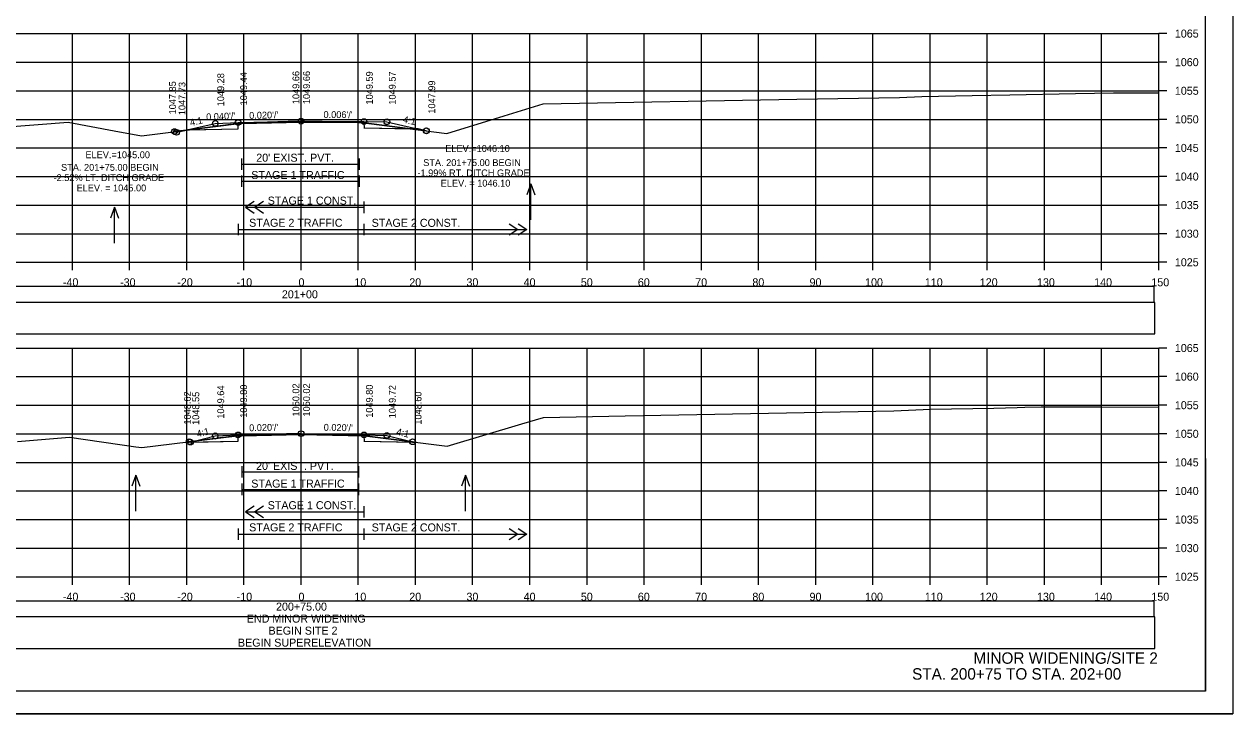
# Model space of a CAD drawing. Extents: x 1370565 to 1374448, y 301010 to 304637.
# Drawn here: x 1373320.4 to 1373531.7, y 301085 to 301205.6 of the extents above; entities that cross this region are included whole.
import ezdxf

# ---------------------------------------------------------------- set-up
doc = ezdxf.new("R2010")
doc.units = 0
for name, color, linetype in [('Default', 7, 'Continuous'), ('R_Alt Surface', 7, 'Continuous'), ('R_Axis', 7, 'Continuous'), ('R_Axis Annot', 7, 'Continuous'), ('R_Border', 7, 'Continuous'), ('R_Contours', 7, 'Continuous'), ('R_Draft', 7, 'Continuous'), ('R_Exist Surface', 7, 'Continuous'), ('R_Fin Surface', 7, 'Continuous'), ('R_Grid', 7, 'Continuous'), ('R_No Plot', 7, 'Continuous'), ('R_Water', 7, 'Continuous'), ('R_Water Annot', 7, 'Continuous'), ('R_Xsect Elev', 7, 'Continuous'), ('R_Xsect Slope', 7, 'Continuous')]:
    doc.layers.add(name, color=color, linetype=linetype)

msp = doc.modelspace()

# ---------------------------------------------------------------- linework, layer by layer
at = {"layer": 'Default'}
for points in [[(1373219.61, 301157), (1373518.02, 301157), (1373518.02, 301159.71), (1373219.61, 301159.71)], [(1373219.61, 301102), (1373518.02, 301102), (1373518.02, 301104.71), (1373219.61, 301104.71)]]:
    msp.add_lwpolyline(points, close=True, dxfattribs=at)
at = {"layer": 'R_Alt Surface'}
for points in [[(1373349.02, 301187.14), (1373357.81, 301187.32), (1373357.8, 301187.32), (1373357.81, 301188.23), (1373368.81, 301188.45), (1373379.81, 301188.39), (1373379.82, 301187.47), (1373379.81, 301187.47), (1373389.26, 301187.28)], [(1373360.61, 301174.57), (1373359.11, 301173.57), (1373360.61, 301172.57)], [(1373362.21, 301174.57), (1373360.71, 301173.57), (1373362.21, 301172.57)], [(1373359.11, 301173.57), (1373379.81, 301173.57)], [(1373357.81, 301170.7), (1373357.81, 301168.7)], [(1373357.81, 301169.7), (1373379.81, 301169.7)], [(1373379.81, 301170.7), (1373379.81, 301168.7)], [(1373379.81, 301170.7), (1373379.81, 301168.7)], [(1373379.81, 301169.7), (1373408.3, 301169.7)], [(1373405.21, 301170.7), (1373406.71, 301169.7), (1373405.21, 301168.7)], [(1373406.8, 301170.7), (1373408.3, 301169.7), (1373406.8, 301168.7)], [(1373348.57, 301132.49), (1373357.81, 301132.68), (1373357.8, 301132.68), (1373357.81, 301133.6), (1373368.81, 301133.82), (1373379.81, 301133.6), (1373379.82, 301132.68), (1373379.81, 301132.68), (1373388.79, 301132.5)], [(1373360.61, 301121.29), (1373359.11, 301120.29), (1373360.61, 301119.29)], [(1373362.21, 301121.29), (1373360.71, 301120.29), (1373362.21, 301119.29)], [(1373359.11, 301120.29), (1373379.81, 301120.29)], [(1373357.81, 301117.42), (1373357.81, 301115.42)], [(1373379.81, 301117.42), (1373379.81, 301115.42)], [(1373379.81, 301117.42), (1373379.81, 301115.42)], [(1373405.21, 301117.42), (1373406.71, 301116.42), (1373405.21, 301115.42)], [(1373406.8, 301117.42), (1373408.3, 301116.42), (1373406.8, 301115.42)], [(1373357.81, 301116.42), (1373379.81, 301116.42)], [(1373379.81, 301116.42), (1373408.3, 301116.42)]]:
    msp.add_lwpolyline(points, dxfattribs=at)
at = {"layer": 'R_Axis'}
for p, q in [((1373518.81, 301163.96), (1373518.81, 301203.96)), ((1373520.21, 301203.96), (1373518.81, 301203.96)), ((1373520.21, 301198.96), (1373518.81, 301198.96)), ((1373520.21, 301193.96), (1373518.81, 301193.96)), ((1373520.21, 301188.96), (1373518.81, 301188.96)), ((1373520.21, 301183.96), (1373518.81, 301183.96)), ((1373520.21, 301178.96), (1373518.81, 301178.96)), ((1373520.21, 301173.96), (1373518.81, 301173.96)), ((1373520.21, 301168.96), (1373518.81, 301168.96)), ((1373218.81, 301163.96), (1373518.81, 301163.96)), ((1373328.81, 301162.56), (1373328.81, 301163.96)), ((1373338.81, 301162.56), (1373338.81, 301163.96)), ((1373348.81, 301162.56), (1373348.81, 301163.96)), ((1373358.81, 301162.56), (1373358.81, 301163.96)), ((1373368.81, 301162.56), (1373368.81, 301163.96)), ((1373378.81, 301162.56), (1373378.81, 301163.96)), ((1373388.81, 301162.56), (1373388.81, 301163.96)), ((1373398.81, 301162.56), (1373398.81, 301163.96)), ((1373408.81, 301162.56), (1373408.81, 301163.96)), ((1373418.81, 301162.56), (1373418.81, 301163.96)), ((1373428.81, 301162.56), (1373428.81, 301163.96)), ((1373438.81, 301162.56), (1373438.81, 301163.96)), ((1373448.81, 301162.56), (1373448.81, 301163.96)), ((1373458.81, 301162.56), (1373458.81, 301163.96)), ((1373468.81, 301162.56), (1373468.81, 301163.96)), ((1373478.81, 301162.56), (1373478.81, 301163.96)), ((1373488.81, 301162.56), (1373488.81, 301163.96)), ((1373498.81, 301162.56), (1373498.81, 301163.96)), ((1373508.81, 301162.56), (1373508.81, 301163.96)), ((1373518.81, 301162.56), (1373518.81, 301163.96)), ((1373520.21, 301163.96), (1373518.81, 301163.96)), ((1373518.81, 301108.96), (1373518.81, 301148.96)), ((1373520.21, 301148.96), (1373518.81, 301148.96)), ((1373520.21, 301143.96), (1373518.81, 301143.96)), ((1373520.21, 301138.96), (1373518.81, 301138.96)), ((1373520.21, 301133.96), (1373518.81, 301133.96)), ((1373520.21, 301128.96), (1373518.81, 301128.96)), ((1373520.21, 301123.96), (1373518.81, 301123.96)), ((1373520.21, 301118.96), (1373518.81, 301118.96)), ((1373520.21, 301113.96), (1373518.81, 301113.96)), ((1373218.81, 301108.96), (1373518.81, 301108.96)), ((1373328.81, 301107.56), (1373328.81, 301108.96)), ((1373338.81, 301107.56), (1373338.81, 301108.96)), ((1373348.81, 301107.56), (1373348.81, 301108.96)), ((1373358.81, 301107.56), (1373358.81, 301108.96)), ((1373368.81, 301107.56), (1373368.81, 301108.96)), ((1373378.81, 301107.56), (1373378.81, 301108.96)), ((1373388.81, 301107.56), (1373388.81, 301108.96)), ((1373398.81, 301107.56), (1373398.81, 301108.96)), ((1373408.81, 301107.56), (1373408.81, 301108.96)), ((1373418.81, 301107.56), (1373418.81, 301108.96)), ((1373428.81, 301107.56), (1373428.81, 301108.96)), ((1373438.81, 301107.56), (1373438.81, 301108.96)), ((1373448.81, 301107.56), (1373448.81, 301108.96)), ((1373458.81, 301107.56), (1373458.81, 301108.96)), ((1373468.81, 301107.56), (1373468.81, 301108.96)), ((1373478.81, 301107.56), (1373478.81, 301108.96)), ((1373488.81, 301107.56), (1373488.81, 301108.96)), ((1373498.81, 301107.56), (1373498.81, 301108.96)), ((1373508.81, 301107.56), (1373508.81, 301108.96)), ((1373518.81, 301107.56), (1373518.81, 301108.96)), ((1373520.21, 301108.96), (1373518.81, 301108.96))]:
    msp.add_line(p, q, dxfattribs=at)
for points in [[(1373358.4, 301182.13), (1373358.4, 301180.13)], [(1373358.4, 301181.13), (1373378.94, 301181.13)], [(1373378.94, 301182.13), (1373378.94, 301180.13)], [(1373358.4, 301179.14), (1373358.4, 301177.14)], [(1373358.4, 301178.14), (1373378.94, 301178.14)], [(1373378.94, 301179.14), (1373378.94, 301177.14)], [(1373379.81, 301174.57), (1373379.81, 301172.57)], [(1373358.43, 301128.32), (1373358.43, 301126.32)], [(1373358.43, 301127.32), (1373378.84, 301127.32)], [(1373378.84, 301128.32), (1373378.84, 301126.32)], [(1373358.43, 301125.24), (1373358.43, 301123.24)], [(1373378.84, 301125.24), (1373378.84, 301123.24)], [(1373358.43, 301124.24), (1373378.84, 301124.24)], [(1373379.81, 301121.29), (1373379.81, 301119.29)]]:
    msp.add_lwpolyline(points, dxfattribs=at)
at = {"layer": 'R_Border'}
for q in [(1373526.99, 301294.42), (1373210.81, 301088.96)]:
    msp.add_line((1373526.99, 301088.96), q, dxfattribs=at)
at = {"layer": 'R_Contours'}
for p, q in [((1373348.75, 301187.08), (1373346.67, 301186.82)), ((1373349.02, 301187.14), (1373348.75, 301187.08)), ((1373348.75, 301187.08), (1373349.02, 301187.12)), ((1373349.02, 301187.12), (1373349.27, 301187.15)), ((1373349.27, 301187.15), (1373349.02, 301187.14)), ((1373357.81, 301188.24), (1373349.27, 301187.15)), ((1373349.27, 301187.15), (1373357.81, 301187.32)), ((1373358.43, 301188.32), (1373357.81, 301188.24)), ((1373357.81, 301188.23), (1373358.43, 301188.25)), ((1373357.81, 301187.32), (1373357.81, 301188.23)), ((1373358.43, 301188.25), (1373368.81, 301188.45)), ((1373368.81, 301188.45), (1373378.84, 301188.39)), ((1373379.55, 301188.39), (1373378.84, 301188.48)), ((1373378.84, 301188.39), (1373379.55, 301188.39)), ((1373379.81, 301188.36), (1373379.82, 301187.47)), ((1373379.82, 301187.47), (1373387.91, 301187.31)), ((1373389.26, 301187.28), (1373387.91, 301187.31)), ((1373387.91, 301187.31), (1373390.69, 301186.95)), ((1373390.69, 301186.96), (1373389.26, 301187.28)), ((1373358.31, 301133.69), (1373357.81, 301133.63)), ((1373357.81, 301133.6), (1373358.29, 301133.6)), ((1373358.29, 301133.6), (1373358.45, 301133.61)), ((1373358.45, 301133.61), (1373368.81, 301133.82)), ((1373368.81, 301133.98), (1373368.81, 301133.82)), ((1373368.81, 301133.82), (1373379.81, 301133.6)), ((1373380.83, 301133.51), (1373379.82, 301133.64)), ((1373348.76, 301132.5), (1373348.95, 301132.5)), ((1373348.95, 301132.5), (1373349.26, 301132.51)), ((1373349.26, 301132.58), (1373348.96, 301132.54)), ((1373349.44, 301132.6), (1373349.26, 301132.58)), ((1373349.26, 301132.58), (1373349.45, 301132.51)), ((1373350.17, 301132.69), (1373349.44, 301132.6)), ((1373349.45, 301132.51), (1373350.17, 301132.69)), ((1373350.17, 301132.69), (1373349.94, 301132.63)), ((1373353.68, 301133.12), (1373350.17, 301132.69)), ((1373388.3, 301132.56), (1373380.83, 301133.51)), ((1373388.31, 301132.56), (1373388.3, 301132.56)), ((1373388.79, 301132.5), (1373388.31, 301132.56)), ((1373388.31, 301132.51), (1373388.79, 301132.5))]:
    msp.add_line(p, q, dxfattribs=at)
for points in [[(1373366.55, 301188.58), (1373361.14, 301188.4), (1373358.43, 301188.32)], [(1373369.3, 301188.62), (1373368.81, 301188.62), (1373368.27, 301188.61), (1373366.55, 301188.58)], [(1373378.84, 301188.48), (1373375.72, 301188.54), (1373369.3, 301188.62)], [(1373346.67, 301186.82), (1373347.04, 301186.69), (1373348.75, 301187.08)], [(1373349.02, 301187.14), (1373349.02, 301187.12)], [(1373349.02, 301187.12), (1373349.02, 301187.14)], [(1373357.81, 301188.23), (1373357.81, 301188.24)], [(1373357.81, 301188.24), (1373357.81, 301188.23)], [(1373358.43, 301188.32), (1373358.43, 301188.25)], [(1373358.43, 301188.25), (1373358.43, 301188.32)], [(1373378.84, 301188.39), (1373378.84, 301188.48)], [(1373378.84, 301188.48), (1373378.84, 301188.39)], [(1373387.91, 301187.31), (1373384.71, 301187.73), (1373379.81, 301188.36)], [(1373390.69, 301186.95), (1373390.69, 301186.96)], [(1373357.81, 301133.63), (1373357.81, 301133.6)], [(1373358.45, 301133.71), (1373358.32, 301133.69), (1373358.31, 301133.69)], [(1373366.28, 301133.93), (1373359.29, 301133.73), (1373358.45, 301133.71)], [(1373358.45, 301133.71), (1373358.45, 301133.61)], [(1373358.45, 301133.61), (1373358.45, 301133.71)], [(1373368.81, 301133.98), (1373368.37, 301133.97), (1373366.28, 301133.93)], [(1373379.82, 301133.64), (1373378.92, 301133.75), (1373377.77, 301133.78), (1373368.81, 301133.98), (1373368.81, 301133.98)], [(1373379.81, 301133.6), (1373379.82, 301133.64)], [(1373379.82, 301133.64), (1373379.81, 301133.6)], [(1373379.81, 301133.6), (1373379.82, 301132.68), (1373388.31, 301132.51)], [(1373348.95, 301132.54), (1373348.76, 301132.52), (1373348.76, 301132.52)], [(1373348.95, 301132.51), (1373348.95, 301132.54)], [(1373348.95, 301132.51), (1373348.95, 301132.5)], [(1373349.26, 301132.51), (1373349.26, 301132.58)], [(1373349.44, 301132.6), (1373349.45, 301132.51)], [(1373349.45, 301132.51), (1373349.44, 301132.6)], [(1373349.95, 301132.52), (1373357.81, 301132.68), (1373357.81, 301133.26)], [(1373357.35, 301133.57), (1373357.15, 301133.55), (1373354.07, 301133.17)], [(1373388.31, 301132.51), (1373388.31, 301132.56)], [(1373388.31, 301132.56), (1373388.31, 301132.56), (1373388.31, 301132.51)]]:
    msp.add_lwpolyline(points, dxfattribs=at)
for centre, start, end in [((1373357.81, 301133.76), 341.6745, 351.6588), ((1373357.81, 301133.76), 341.6745, 351.6588), ((1373349.26, 301132.58), 187.0089, 189.2983), ((1373349.45, 301132.51), 176.614, 180), ((1373349.45, 301132.51), 180, 181.2068), ((1373349.45, 301132.51), 1.0848, 14.0363), ((1373353.81, 301133.6), 253.8235, 300.1943), ((1373357.81, 301133.76), 202.1604, 270)]:
    msp.add_arc(centre, 0.5, start, end, dxfattribs=at)
at = {"layer": 'R_Exist Surface'}
for points in [[(1373304.79, 301186.66), (1373328.1, 301188.49), (1373336.1, 301186.95), (1373340.9, 301186.09), (1373344.16, 301186.49), (1373358.43, 301188.32), (1373361.14, 301188.4), (1373368.27, 301188.63), (1373375.72, 301188.54), (1373378.84, 301188.48), (1373384.71, 301187.73), (1373394.27, 301186.49), (1373404.35, 301189.56), (1373411.16, 301191.65), (1373455.5, 301192.51), (1373473.46, 301192.8), (1373477.34, 301192.94), (1373486.19, 301193.15), (1373492.75, 301193.27), (1373504.23, 301193.48), (1373510.87, 301193.62), (1373511.82, 301193.62), (1373518.81, 301193.62)], [(1373319.24, 301132.6), (1373328.29, 301133.38), (1373339.91, 301131.69), (1373340.99, 301131.56), (1373357.15, 301133.55), (1373358.45, 301133.71), (1373359.29, 301133.73), (1373368.37, 301133.99), (1373377.77, 301133.78), (1373378.92, 301133.75), (1373380.83, 301133.51), (1373394.35, 301131.79), (1373407.39, 301135.7), (1373411.22, 301136.83), (1373425.48, 301137.09), (1373472.49, 301137.98), (1373478.85, 301138.24), (1373489.93, 301138.46), (1373494.01, 301138.58), (1373495.39, 301138.61), (1373498.22, 301138.66), (1373508.74, 301138.66), (1373518.81, 301138.61)]]:
    msp.add_lwpolyline(points, dxfattribs=at)
at = {"layer": 'R_Fin Surface'}
for points in [[(1373346.67, 301186.82), (1373347.04, 301186.69), (1373353.81, 301188.24), (1373357.81, 301188.4), (1373368.81, 301188.62), (1373379.81, 301188.56), (1373383.81, 301188.53), (1373390.69, 301186.96), (1373390.72, 301186.95)], [(1373349.26, 301132.58), (1373349.45, 301132.51), (1373353.81, 301133.6), (1373357.81, 301133.76), (1373368.81, 301133.98), (1373379.81, 301133.76), (1373383.81, 301133.68), (1373388.31, 301132.56), (1373388.32, 301132.56)]]:
    msp.add_lwpolyline(points, dxfattribs=at)
for points in [[(1373219.66, 301151.42), (1373518.08, 301151.42), (1373518.08, 301156.94), (1373219.66, 301156.94)], [(1373219.66, 301096.43), (1373518.08, 301096.43), (1373518.08, 301101.95), (1373219.66, 301101.95)]]:
    msp.add_lwpolyline(points, close=True, dxfattribs=at)
at = {"layer": 'R_Grid'}
for p, q in [((1373218.81, 301203.96), (1373518.81, 301203.96)), ((1373328.81, 301163.96), (1373328.81, 301203.96)), ((1373338.81, 301163.96), (1373338.81, 301203.96)), ((1373348.81, 301163.96), (1373348.81, 301203.96)), ((1373358.81, 301163.96), (1373358.81, 301203.96)), ((1373368.81, 301163.96), (1373368.81, 301203.96)), ((1373378.81, 301163.96), (1373378.81, 301203.96)), ((1373388.81, 301163.96), (1373388.81, 301203.96)), ((1373398.81, 301163.96), (1373398.81, 301203.96)), ((1373408.81, 301163.96), (1373408.81, 301203.96)), ((1373418.81, 301163.96), (1373418.81, 301203.96)), ((1373428.81, 301163.96), (1373428.81, 301203.96)), ((1373438.81, 301163.96), (1373438.81, 301203.96)), ((1373448.81, 301163.96), (1373448.81, 301203.96)), ((1373458.81, 301163.96), (1373458.81, 301203.96)), ((1373468.81, 301163.96), (1373468.81, 301203.96)), ((1373478.81, 301163.96), (1373478.81, 301203.96)), ((1373488.81, 301163.96), (1373488.81, 301203.96)), ((1373498.81, 301163.96), (1373498.81, 301203.96)), ((1373508.81, 301163.96), (1373508.81, 301203.96)), ((1373518.81, 301163.96), (1373518.81, 301203.96)), ((1373218.81, 301198.96), (1373518.81, 301198.96)), ((1373218.81, 301193.96), (1373518.81, 301193.96)), ((1373218.81, 301188.96), (1373518.81, 301188.96)), ((1373218.81, 301183.96), (1373518.81, 301183.96)), ((1373218.81, 301178.96), (1373518.81, 301178.96)), ((1373218.81, 301173.96), (1373518.81, 301173.96)), ((1373218.81, 301168.96), (1373518.81, 301168.96)), ((1373218.81, 301163.96), (1373518.81, 301163.96)), ((1373218.81, 301148.96), (1373518.81, 301148.96)), ((1373328.81, 301108.96), (1373328.81, 301148.96)), ((1373338.81, 301108.96), (1373338.81, 301148.96)), ((1373348.81, 301108.96), (1373348.81, 301148.96)), ((1373358.81, 301108.96), (1373358.81, 301148.96)), ((1373368.81, 301108.96), (1373368.81, 301148.96)), ((1373378.81, 301108.96), (1373378.81, 301148.96)), ((1373388.81, 301108.96), (1373388.81, 301148.96)), ((1373398.81, 301108.96), (1373398.81, 301148.96)), ((1373408.81, 301108.96), (1373408.81, 301148.96)), ((1373418.81, 301108.96), (1373418.81, 301148.96)), ((1373428.81, 301108.96), (1373428.81, 301148.96)), ((1373438.81, 301108.96), (1373438.81, 301148.96)), ((1373448.81, 301108.96), (1373448.81, 301148.96)), ((1373458.81, 301108.96), (1373458.81, 301148.96)), ((1373468.81, 301108.96), (1373468.81, 301148.96)), ((1373478.81, 301108.96), (1373478.81, 301148.96)), ((1373488.81, 301108.96), (1373488.81, 301148.96)), ((1373498.81, 301108.96), (1373498.81, 301148.96)), ((1373508.81, 301108.96), (1373508.81, 301148.96)), ((1373518.81, 301108.96), (1373518.81, 301148.96)), ((1373218.81, 301143.96), (1373518.81, 301143.96)), ((1373218.81, 301138.96), (1373518.81, 301138.96)), ((1373218.81, 301133.96), (1373518.81, 301133.96)), ((1373218.81, 301128.96), (1373518.81, 301128.96)), ((1373218.81, 301123.96), (1373518.81, 301123.96)), ((1373218.81, 301118.96), (1373518.81, 301118.96)), ((1373218.81, 301113.96), (1373518.81, 301113.96)), ((1373218.81, 301108.96), (1373518.81, 301108.96))]:
    msp.add_line(p, q, dxfattribs=at)
at = {"layer": 'R_No Plot'}
msp.add_line((1373198.41, 301084.98), (1373531.75, 301084.98), dxfattribs=at)
for points in [[(1373198.41, 301298.32), (1373531.75, 301298.32), (1373531.75, 301084.98), (1373198.41, 301084.98)], [(1373444.73, 301294.42), (1373464.35, 301294.42), (1373464.35, 301284.54), (1373480.47, 301284.54), (1373503.67, 301284.54), (1373503.67, 301251.87), (1373526.87, 301251.87), (1373526.99, 301088.96), (1373210.81, 301088.96), (1373210.81, 301294.42)]]:
    msp.add_lwpolyline(points, close=True, dxfattribs=at)
for centre in [(1373353.81, 301188.24), (1373357.81, 301188.4), (1373368.81, 301188.62), (1373379.81, 301188.56), (1373383.81, 301188.53), (1373346.67, 301186.82), (1373347.04, 301186.69), (1373390.69, 301186.96), (1373390.72, 301186.95), (1373353.81, 301133.6), (1373357.81, 301133.76), (1373368.81, 301133.98), (1373379.81, 301133.76), (1373383.81, 301133.68), (1373349.26, 301132.58), (1373349.45, 301132.51), (1373388.31, 301132.56), (1373388.32, 301132.56)]:
    msp.add_circle(centre, 0.5, dxfattribs=at)
at = {"layer": 'R_Water Annot'}
for p, q in [((1373408.97, 301177.66), (1373408.27, 301175.74)), ((1373408.97, 301171.38), (1373408.97, 301177.66)), ((1373408.97, 301177.66), (1373409.67, 301175.74)), ((1373336.16, 301173.58), (1373335.46, 301171.65)), ((1373336.16, 301167.29), (1373336.16, 301173.58)), ((1373336.16, 301173.58), (1373336.86, 301171.65)), ((1373339.89, 301126.71), (1373339.19, 301124.79)), ((1373339.89, 301120.43), (1373339.89, 301126.71)), ((1373339.89, 301126.71), (1373340.59, 301124.79)), ((1373397.57, 301126.71), (1373396.87, 301124.79)), ((1373397.57, 301120.43), (1373397.57, 301126.71)), ((1373397.57, 301126.71), (1373398.27, 301124.79))]:
    msp.add_line(p, q, dxfattribs=at)
at = {"layer": 'R_Xsect Elev'}
for p, q in [((1373368.81, 301188.62), (1373368.81, 301198.62)), ((1373368.81, 301133.98), (1373368.81, 301143.98))]:
    msp.add_line(p, q, dxfattribs=at)

# ---------------------------------------------------------------- texts
at = {"layer": 'R_Axis Annot'}
for s, p in [('1065', (1373521.61, 301203.26)), ('1060', (1373521.61, 301198.26)), ('1055', (1373521.61, 301193.26)), ('1050', (1373521.61, 301188.26)), ('1045', (1373521.61, 301183.26)), ("20' EXIST. PVT.", (1373360.97, 301181.55)), ('1040', (1373521.61, 301178.26)), ('1035', (1373521.61, 301173.26)), ('1030', (1373521.61, 301168.26)), ('1025', (1373521.61, 301163.26)), ('-40', (1373327.16, 301159.76)), ('-30', (1373337.16, 301159.76)), ('-20', (1373347.16, 301159.76)), ('-10', (1373357.55, 301159.76)), ('0', (1373368.36, 301159.76)), ('10', (1373378.13, 301159.76)), ('20', (1373387.73, 301159.76)), ('30', (1373397.73, 301159.76)), ('40', (1373407.73, 301159.76)), ('50', (1373417.73, 301159.76)), ('60', (1373427.7, 301159.76)), ('70', (1373437.73, 301159.76)), ('80', (1373447.73, 301159.76)), ('90', (1373457.73, 301159.76)), ('100', (1373467.44, 301159.76)), ('110', (1373477.89, 301159.76)), ('120', (1373487.5, 301159.76)), ('130', (1373497.5, 301159.76)), ('140', (1373507.5, 301159.76)), ('150', (1373517.5, 301159.76)), ('201+00', (1373365.45, 301157.66)), ('1065', (1373521.61, 301148.26)), ('1060', (1373521.61, 301143.26)), ('1055', (1373521.61, 301138.26)), ('1050', (1373521.61, 301133.26)), ('1045', (1373521.61, 301128.26)), ("20' EXIST. PVT.", (1373360.94, 301127.64)), ('1040', (1373521.61, 301123.26)), ('1035', (1373521.61, 301118.26)), ('1030', (1373521.61, 301113.26)), ('1025', (1373521.61, 301108.26)), ('-40', (1373327.16, 301104.76)), ('-30', (1373337.16, 301104.76)), ('-20', (1373347.16, 301104.76)), ('-10', (1373357.55, 301104.76)), ('0', (1373368.36, 301104.76)), ('10', (1373378.13, 301104.76)), ('20', (1373387.73, 301104.76)), ('30', (1373397.73, 301104.76)), ('40', (1373407.73, 301104.76)), ('50', (1373417.73, 301104.76)), ('60', (1373427.7, 301104.76)), ('70', (1373437.73, 301104.76)), ('80', (1373447.73, 301104.76)), ('90', (1373457.73, 301104.76)), ('100', (1373467.44, 301104.76)), ('110', (1373477.89, 301104.76)), ('120', (1373487.5, 301104.76)), ('130', (1373497.5, 301104.76)), ('140', (1373507.5, 301104.76)), ('150', (1373517.5, 301104.76)), ('200+75.00', (1373364.43, 301103.03)), ('END MINOR WIDENING', (1373359.32, 301100.93)), ('BEGIN SITE 2', (1373363.11, 301098.83)), ('BEGIN SUPERELEVATION', (1373357.77, 301096.73))]:
    msp.add_text(s, height=1.4, dxfattribs=at).set_placement(p)
at = {"layer": 'R_Draft'}
for s, p in [('MINOR WIDENING/SITE 2', (1373486.39, 301093.73)), ('STA. 200+75 TO STA. 202+00', (1373475.66, 301090.96))]:
    msp.add_text(s, height=2, dxfattribs=at).set_placement(p)
at = {"layer": 'R_Water'}
for s, p in [('STAGE 1 TRAFFIC', (1373360.1, 301178.52)), ('STAGE 1 CONST.', (1373362.97, 301174.05)), ('STAGE 2 TRAFFIC', (1373359.73, 301170.17)), ('STAGE 2 CONST.', (1373381.15, 301170.16)), ('STAGE 1 TRAFFIC', (1373360.1, 301124.55)), ('STAGE 1 CONST.', (1373362.97, 301120.77)), ('STAGE 2 TRAFFIC', (1373359.73, 301116.89)), ('STAGE 2 CONST.', (1373381.15, 301116.88))]:
    msp.add_text(s, height=1.4, dxfattribs=at).set_placement(p)
at = {"layer": 'R_Xsect Elev'}
for s, p in [('1049.44', (1373359.36, 301191.4)), ('1049.66', (1373368.51, 301191.62)), ('1049.66', (1373370.36, 301191.62)), ('1049.59', (1373381.36, 301191.56)), ('1049.57', (1373385.36, 301191.53)), ('1047.85', (1373346.93, 301189.82)), ('1047.73', (1373348.59, 301189.69)), ('1049.28', (1373355.36, 301191.24)), ('1047.99', (1373392.27, 301189.95)), ('1049.64', (1373355.36, 301136.6)), ('1049.80', (1373359.36, 301136.76)), ('1050.02', (1373368.51, 301136.98)), ('1050.02', (1373370.36, 301136.98)), ('1049.80', (1373381.36, 301136.76)), ('1049.72', (1373385.36, 301136.68)), ('1048.62', (1373349.53, 301135.58)), ('1048.55', (1373351, 301135.51)), ('1048.60', (1373389.87, 301135.56)), ('1048.60', (1373389.86, 301135.56))]:
    msp.add_text(s, height=1.2, rotation=90, dxfattribs=at).set_placement(p)
for s, p in [('ELEV.=1046.10', (1373394.02, 301183.26)), ('ELEV.=1045.00', (1373331.1, 301182.16)), ('STA. 201+75.00 BEGIN ', (1373326.84, 301179.96)), ('-1.99% RT. DITCH GRADE', (1373389.16, 301178.99)), ('STA. 201+75.00 BEGIN ', (1373390.17, 301180.79)), ('-2.52% LT. DITCH GRADE', (1373325.52, 301178.16)), ('ELEV. = 1046.10', (1373393.23, 301177.19)), ('ELEV. = 1045.00', (1373329.55, 301176.36))]:
    msp.add_text(s, height=1.2, dxfattribs=at).set_placement(p)
at = {"layer": 'R_Xsect Slope'}
for s, rotation, p in [('4:1', 12.9079, (1373349.51, 301187.77)), ("0.040'/'", 2.2906, (1373352.23, 301188.78)), ("0.020'/'", 1.1458, (1373359.74, 301189.04)), ("0.006'/'", 359.6562, (1373372.73, 301189.2)), ('4:1', 347.0921, (1373386.55, 301188.42)), ("0.020'/'", 1.1458, (1373359.74, 301134.4)), ("0.020'/'", 358.8542, (1373372.76, 301134.5)), ('4:1', 14.0362, (1373350.71, 301133.34)), ('4:1', 345.9638, (1373385.38, 301133.81))]:
    msp.add_text(s, height=1.2, rotation=rotation, dxfattribs=at).set_placement(p)

doc.saveas('drawing.dxf')
